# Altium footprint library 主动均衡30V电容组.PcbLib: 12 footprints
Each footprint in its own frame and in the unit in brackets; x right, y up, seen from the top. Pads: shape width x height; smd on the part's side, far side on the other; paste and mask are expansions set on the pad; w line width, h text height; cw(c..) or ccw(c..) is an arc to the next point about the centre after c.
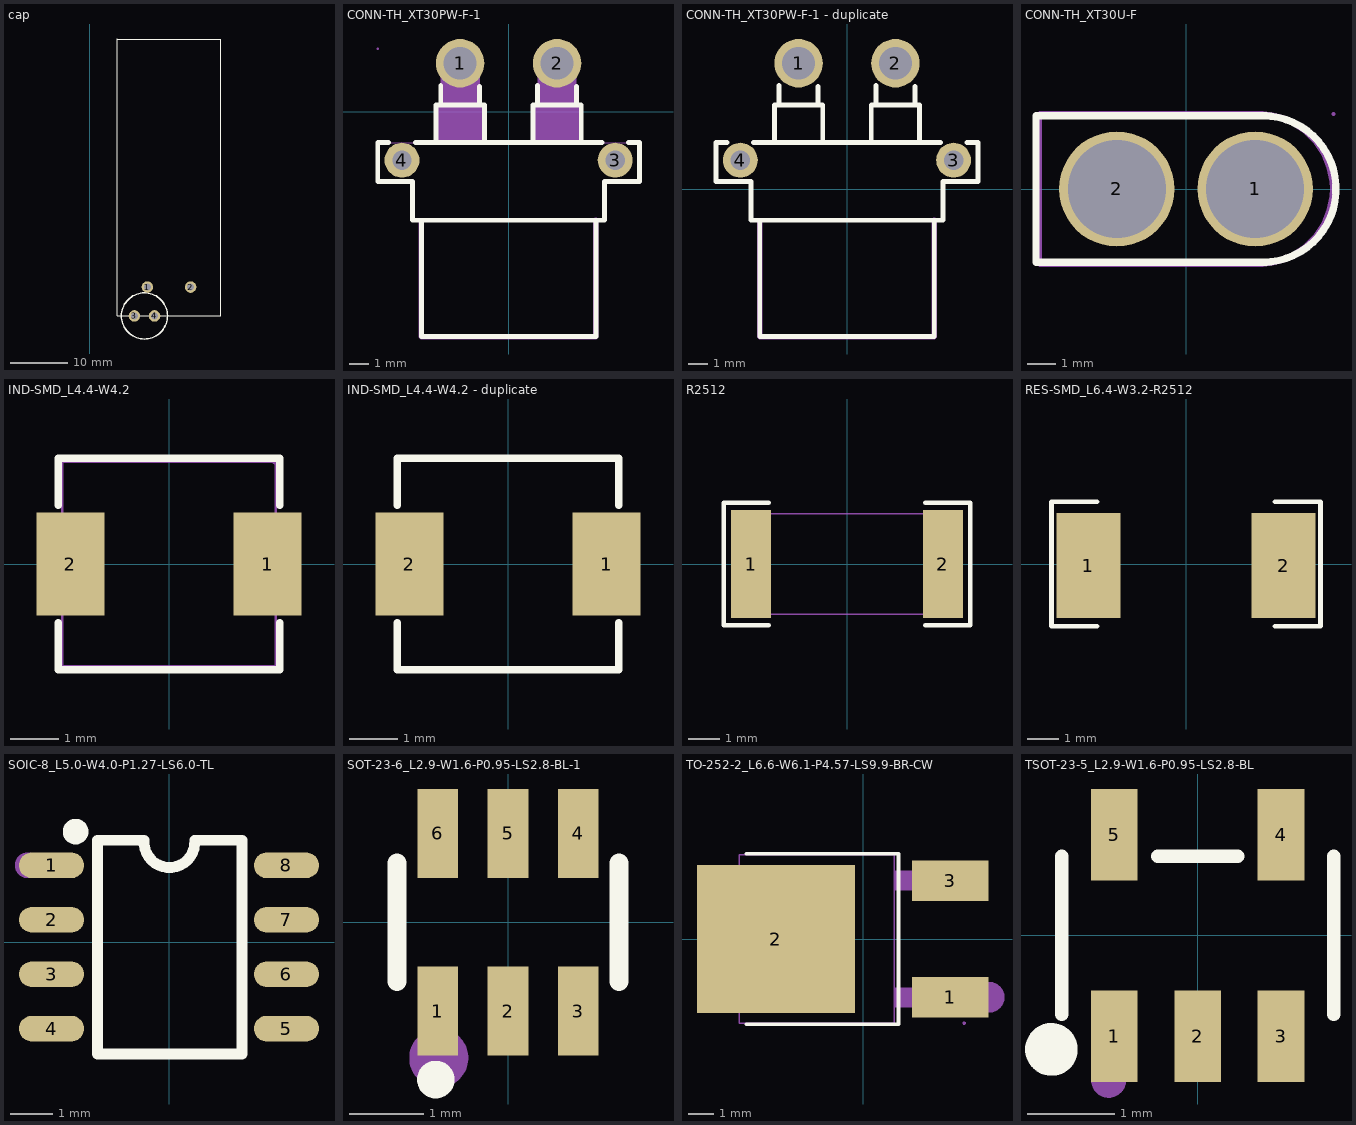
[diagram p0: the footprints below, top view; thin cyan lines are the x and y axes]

## cap [mm]
pads (4):
  round 2 hole 1.2: 1(10,12.033) 2(17.5,12.033) 3(7.75,7.033) 4(11.25,7.033)
Top Overlay:
  circle w0.254: c9.5,7.033 r4
  lines w0.152: 4.75,7.033 22.75,7.033 22.75,55.033 4.75,55.033 4.75,7.033

## CONN-TH_XT30PW-F-1 [mm]
pads (4):
  round 2.5 hole 1.7 copper offset 0,0: 1(-2.5,2.5) 2(2.5,2.5)
  round 1.8 hole 1 copper offset 0,0: 3(5.5,-2.5) 4(-5.5,-2.5)
Top Overlay:
  lines w0.254: -6.184,-1.6 -6.75,-1.6 -6.75,-3.6 -4.95,-3.6 -4.95,-5.6 4.95,-5.6 4.95,-3.6 6.75,-3.6 6.75,-1.6 6.184,-1.6 ; -4.816,-1.6 4.816,-1.6 ; -4.5,-5.6 -4.5,-11.6 4.5,-11.6 4.5,-5.6 ; -3.75,-1.6 -3.75,0.35 -1.25,0.35 -1.25,-1.6 ; -3.5,0.35 -3.5,1.347 ; -1.5,0.35 -1.5,1.297 ; 1.25,-1.6 1.25,0.35 3.75,0.35 3.75,-1.6 ; 1.5,0.35 1.5,1.347 ; 3.5,0.35 3.5,1.297
Mechanical 6:
  region: -4.373,-5.62 -4.373,-11.473 4.373,-11.473 4.373,-5.6 4.373,-5.547 4.447,-5.473 4.553,-5.473 4.627,-5.547 4.627,-5.6 4.627,-11.6 4.627,-11.625 4.608,-11.672 4.572,-11.708 4.525,-11.727 4.5,-11.727 -4.5,-11.727 -4.525,-11.727 -4.572,-11.708 -4.608,-11.672 -4.627,-11.625 -4.627,-11.6 -4.627,-5.62 -4.627,-5.567 -4.553,-5.493 -4.447,-5.493 -4.373,-5.567 -4.373,-5.62
Mechanical 15:
  region: -6.69,3.25 -6.69,3.275 -6.725,3.31 -6.775,3.31 -6.81,3.275 -6.81,3.25 -6.81,3.225 -6.775,3.19 -6.725,3.19 -6.69,3.225 -6.69,3.25
  region: -5.1,-2.5 -5.101,-2.421 -5.163,-2.276 -5.275,-2.165 -5.421,-2.106 -5.579,-2.106 -5.725,-2.165 -5.837,-2.276 -5.899,-2.421 -5.9,-2.5 -5.899,-2.579 -5.837,-2.724 -5.725,-2.834 -5.579,-2.894 -5.421,-2.894 -5.275,-2.835 -5.163,-2.724 -5.101,-2.579 -5.1,-2.5
  region: 5.9,-2.5 5.899,-2.421 5.837,-2.276 5.725,-2.165 5.579,-2.106 5.421,-2.106 5.275,-2.165 5.163,-2.276 5.101,-2.421 5.1,-2.5 5.101,-2.579 5.163,-2.724 5.275,-2.834 5.421,-2.894 5.579,-2.894 5.725,-2.835 5.837,-2.724 5.899,-2.579 5.9,-2.5
  region: 3.25,2.5 3.249,2.598 3.197,2.787 3.097,2.956 2.958,3.094 2.788,3.192 2.598,3.242 2.402,3.242 2.212,3.192 2.042,3.094 1.903,2.956 1.804,2.787 1.751,2.598 1.75,2.5 1.751,2.402 1.803,2.213 1.903,2.044 2.042,1.906 2.212,1.808 2.402,1.758 2.598,1.758 2.788,1.808 2.958,1.906 3.097,2.044 3.197,2.213 3.249,2.402 3.25,2.5
  region: -1.75,2.5 -1.751,2.598 -1.803,2.787 -1.903,2.956 -2.042,3.094 -2.212,3.192 -2.402,3.242 -2.598,3.242 -2.788,3.192 -2.958,3.094 -3.097,2.956 -3.196,2.787 -3.249,2.598 -3.25,2.5 -3.249,2.402 -3.196,2.213 -3.097,2.044 -2.958,1.906 -2.788,1.808 -2.598,1.758 -2.402,1.758 -2.212,1.808 -2.042,1.906 -1.903,2.044 -1.803,2.213 -1.751,2.402 -1.75,2.5
  region: -3.75,-1.65 -3.75,0.35 -3.5,0.35 -3.5,3.25 -1.5,3.25 -1.5,0.35 -1.25,0.35 -1.25,-1.65
  region: 1.25,-1.65 1.25,0.35 1.5,0.35 1.5,3.25 3.5,3.25 3.5,0.35 3.75,0.35 3.75,-1.65
  lines w0.051: -6.75,-3.6 -6.75,-1.6 6.75,-1.6 6.75,-3.6 4.95,-3.6 4.95,-5.6 4.5,-5.6 4.5,-11.6 -4.5,-11.6 -4.5,-5.6 -4.95,-5.6 -4.95,-3.6 -6.75,-3.6

## CONN-TH_XT30PW-F-1 - duplicate [mm]
pads (4):
  round 2.5 hole 1.7 paste-2539.97 mask+0.051: 1(-2.5,6.488) 2(2.5,6.488)
  round 1.8 hole 1 paste-2539.97 mask+0.051: 3(5.5,1.488) 4(-5.5,1.488)
Top Overlay:
  lines w0.254: -6.184,2.389 -6.75,2.389 -6.75,0.389 -4.95,0.389 -4.95,-1.611 4.95,-1.611 4.95,0.389 6.75,0.389 6.75,2.389 6.184,2.389 ; -4.816,2.389 4.816,2.389 ; -4.5,-1.611 -4.5,-7.611 4.5,-7.611 4.5,-1.611 ; -3.75,2.389 -3.75,4.339 -1.25,4.339 -1.25,2.389 ; -3.5,4.339 -3.5,5.336 ; -1.5,4.339 -1.5,5.285 ; 1.25,2.388 1.25,4.338 3.75,4.338 3.75,2.388 ; 1.5,4.338 1.5,5.336 ; 3.5,4.338 3.5,5.285
Mechanical 15:
  region: -4.373,-1.631 -4.373,-7.484 4.373,-7.484 4.373,-1.611 4.373,-1.559 4.447,-1.484 4.553,-1.484 4.627,-1.559 4.627,-1.611 4.627,-7.611 4.627,-7.637 4.608,-7.683 4.572,-7.719 4.525,-7.738 4.5,-7.738 -4.5,-7.738 -4.525,-7.738 -4.572,-7.719 -4.608,-7.683 -4.627,-7.637 -4.627,-7.611 -4.627,-1.631 -4.627,-1.579 -4.553,-1.504 -4.447,-1.504 -4.373,-1.579 -4.373,-1.631

## CONN-TH_XT30U-F [mm]
pads (2):
  round 4 hole 3.4: 1(2.4,0) 2(-2.4,0)
Top Overlay:
  lines w0.254: 2.667,-2.54 ccw(c2.667,0) 2.667,2.54 ; 2.794,-2.54 -5.207,-2.54 -5.207,2.54 2.794,2.54
Mechanical 6:
  region: 2.5,2.7 -5.1,2.7 -5.2,2.6 -5.2,-2.6 -5.1,-2.7 2.5,-2.7 2.5,-2.5 -5,-2.5 -5,2.5 2.5,2.5
  region: 2.5,-2.5 2.745,-2.488 3.226,-2.392 3.678,-2.205 4.086,-1.932 4.432,-1.586 4.705,-1.178 4.892,-0.726 4.988,-0.245 5,0 5.2,0 5.2,-0.177 5.154,-0.528 5.062,-0.87 4.927,-1.197 4.75,-1.503 4.534,-1.784 4.284,-2.034 4.003,-2.25 3.697,-2.427 3.37,-2.562 3.028,-2.654 2.677,-2.7 2.5,-2.7
  region: 5,0 4.988,0.245 4.892,0.726 4.705,1.179 4.432,1.586 4.086,1.933 3.678,2.205 3.226,2.392 2.745,2.488 2.5,2.5 2.5,2.7 2.677,2.7 3.028,2.654 3.37,2.562 3.697,2.427 4.003,2.25 4.284,2.034 4.534,1.784 4.75,1.503 4.927,1.197 5.062,0.87 5.154,0.528 5.2,0.177 5.2,0
Mechanical 15:
  region: 5.174,2.6 5.174,2.625 5.139,2.66 5.089,2.66 5.054,2.625 5.054,2.6 5.054,2.575 5.089,2.54 5.139,2.54 5.174,2.575 5.174,2.6
  region: -1.5,0 -1.5,0.132 -1.568,0.386 -1.7,0.614 -1.886,0.8 -2.114,0.932 -2.368,1 -2.632,1 -2.886,0.932 -3.114,0.8 -3.3,0.614 -3.432,0.386 -3.5,0.132 -3.5,0 -3.5,-0.132 -3.432,-0.386 -3.3,-0.614 -3.114,-0.8 -2.886,-0.932 -2.632,-1 -2.368,-1 -2.114,-0.932 -1.886,-0.8 -1.7,-0.614 -1.568,-0.386 -1.5,-0.132 -1.5,0
  region: 3.5,0 3.5,0.132 3.432,0.386 3.3,0.614 3.114,0.8 2.886,0.932 2.632,1 2.368,1 2.114,0.932 1.886,0.8 1.7,0.614 1.568,0.386 1.5,0.132 1.5,0 1.5,-0.132 1.568,-0.386 1.7,-0.614 1.886,-0.8 2.114,-0.932 2.368,-1 2.632,-1 2.886,-0.932 3.114,-0.8 3.3,-0.614 3.432,-0.386 3.5,-0.132 3.5,0
  lines w0.051: -5.1,-2.6 -5.1,2.52 cw(c-5.08,2.52) -5.08,2.54 2.514,2.6 cw(c2.514,0) 5.114,0 cw(c2.514,0) 2.514,-2.6 -5.1,-2.6

## IND-SMD_L4.4-W4.2 [mm]
pads (2):
  rect 1.4x2.12 smd: 1(2.028,0) 2(-2.028,0)
Top Overlay:
  lines w0.152: -2.276,-1.212 -2.276,-2.176 2.276,-2.176 2.276,-1.212 ; -2.276,1.212 -2.276,2.176 2.276,2.176 2.276,1.212
Mechanical 15:
  region: -2.2,1 -1.4,1 -1.4,-1 -2.2,-1
  region: 1.4,1 2.2,1 2.2,-1 1.4,-1
  region: 2.26,2.1 2.259,2.124 2.224,2.158 2.176,2.158 2.141,2.124 2.14,2.1 2.141,2.076 2.176,2.042 2.224,2.042 2.259,2.076 2.26,2.1
  lines w0.051: -2.2,-2.1 2.2,-2.1 2.2,2.1 -2.2,2.1 -2.2,-2.1

## IND-SMD_L4.4-W4.2 - duplicate [mm]
pads (2):
  rect 1.4x2.12 smd paste+0 mask+0.051: 1(2.028,0) 2(-2.028,0)
Top Overlay:
  lines w0.152: -2.276,-1.212 -2.276,-2.176 2.276,-2.176 2.276,-1.212 ; -2.276,1.212 -2.276,2.176 2.276,2.176 2.276,1.212

## R2512 [mm]
pads (2):
  rect 1.283x3.456 smd paste-100 mask+0.051: 1(-3.066,0) 2(3.066,0)
Top Overlay:
  lines w0.152: -2.501,-1.957 -3.936,-1.957 -3.936,1.957 -2.501,1.957 ; 2.501,-1.957 3.936,-1.957 3.936,1.957 2.501,1.957
Top Paste:
  region: 2.425,-1.628 2.425,-0.688 2.525,-0.588 2.761,-0.588 2.861,-0.488 2.861,0.488 2.761,0.588 2.525,0.588 2.425,0.688 2.425,1.628 2.525,1.728 3.608,1.728 3.708,1.628 3.708,-1.628 3.608,-1.728 2.525,-1.728
  region: -2.425,-1.628 -2.425,-0.688 -2.525,-0.588 -2.761,-0.588 -2.861,-0.488 -2.861,0.488 -2.761,0.588 -2.525,0.588 -2.425,0.688 -2.425,1.628 -2.525,1.728 -3.608,1.728 -3.708,1.628 -3.708,-1.628 -3.608,-1.728 -2.525,-1.728
Mechanical 15:
  region: -3.115,-1.6 -3.115,-1.575 -3.15,-1.54 -3.2,-1.54 -3.235,-1.575 -3.235,-1.6 -3.235,-1.625 -3.2,-1.66 -3.15,-1.66 -3.115,-1.625 -3.115,-1.6
  region: -3.15,-1.6 -3.15,1.6 -2.55,1.6 -2.55,-1.6
  region: 2.55,-1.6 2.55,1.6 3.15,1.6 3.15,-1.6
  lines w0.051: -3.15,-1.6 -3.15,1.6 3.15,1.6 3.15,-1.6 -3.15,-1.6

## RES-SMD_L6.4-W3.2-R2512 [mm]
pads (2):
  rect 2x3.3 smd paste+0 mask+0.051: 1(-3.066,-0.052) 2(3.066,-0.052)
Top Overlay:
  lines w0.152: -2.794,-1.957 -4.229,-1.957 -4.229,1.957 -2.794,1.957 ; 2.794,-1.957 4.229,-1.957 4.229,1.957 2.794,1.957

## SOIC-8_L5.0-W4.0-P1.27-LS6.0-TL [mm]
pads (8):
  oval 1.52x0.6 smd paste+0 mask+0.051: 1(-2.74,1.798) 2(-2.74,0.528) 3(-2.74,-0.742) 4(-2.74,-2.012) 5(2.74,-2.012) 6(2.74,-0.742) 7(2.74,0.528) 8(2.74,1.798)
Top Overlay:
  lines w0.254: -1.671,-2.607 1.7,-2.607 1.7,2.383 0.6,2.383 cw(c0.01,2.338) -0.58,2.383 -1.671,2.383 -1.671,-2.607
  lines w0.3: -2.029,2.583 cw(c-2.179,2.584) -2.029,2.585
Mechanical 15:
  circle w0.3: c-3.299,1.798 r0.15

## SOT-23-6_L2.9-W1.6-P0.95-LS2.8-BL-1 [mm]
pads (6):
  rect 0.55x1.2 smd: 1(-0.95,-1.2) 2(0,-1.2) 3(0.95,-1.2) 4(0.95,1.2) 5(0,1.2) 6(-0.95,1.2)
Top Overlay:
  circle w0.254: c-0.975,-2.125 r0.127
  lines w0.254: -1.5,-0.8 -1.5,0.8 ; 1.5,-0.8 1.5,0.8
Mechanical 15:
  circle w0.4: c-0.934,-1.832 r0.2

## TO-252-2_L6.6-W6.1-P4.57-LS9.9-BR-CW [mm]
pads (3):
  rect 3x1.6 smd: 1(3.424,-2.29) 3(3.424,2.29)
  rect 6.2x5.8 smd: 2(-3.424,0)
Top Overlay:
  lines w0.152: -4.585,-3.346 1.383,-3.346 1.383,3.346 -4.585,3.346
Mechanical 6:
  circle w0.6: c4.953,-2.286 r0.3
Mechanical 15:
  region: -4.954,2.505 -0.938,2.505 -0.938,-2.505 -4.954,-2.505 -5.954,-1.505 -5.954,1.505
  region: 2.371,1.91 2.371,2.67 3.961,2.67 3.961,1.91
  region: 1.211,1.91 1.211,2.67 2.381,2.67 2.381,1.91
  region: 2.371,-2.67 2.371,-1.91 3.961,-1.91 3.961,-2.67
  region: 1.211,-2.67 1.211,-1.91 2.381,-1.91 2.381,-2.67
  region: 4.021,-3.3 4.021,-3.275 3.986,-3.24 3.937,-3.24 3.901,-3.275 3.901,-3.3 3.901,-3.325 3.937,-3.36 3.986,-3.36 4.021,-3.325 4.021,-3.3
  lines w0.051: -4.874,-3.3 -4.874,3.3 1.221,3.3 1.221,-3.3 -4.874,-3.3

## TSOT-23-5_L2.9-W1.6-P0.95-LS2.8-BL [mm]
pads (5):
  rect 0.532x1.045 smd: 1(-0.95,-1.147) 2(0,-1.147) 3(0.95,-1.147) 4(0.95,1.147) 5(-0.95,1.147)
Top Overlay:
  circle w0.3: c-1.668,-1.3 r0.15
  lines w0.152: -1.551,-0.901 -1.551,0.901 ; -0.455,0.901 0.455,0.901 ; 1.551,-0.901 1.551,0.901
Mechanical 15:
  circle w0.2: c-1.016,-1.651 r0.1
